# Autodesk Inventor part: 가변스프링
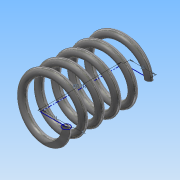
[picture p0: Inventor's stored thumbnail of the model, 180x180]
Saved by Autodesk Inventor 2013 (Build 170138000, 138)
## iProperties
Created: 2019-10
Part Number: 가변스프링
Material: 스테인리스강
Document SubType Name: Modeling
Designer: Administrator
Density: 8.08 g/cm^3
Mass: 147.816 g
Surface Area: 124.166 cm^2
Volume: 18.294 cm^3
Author: Administrator
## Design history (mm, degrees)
sketch "스케치1"
  geometry: L1 (0, 0)-(21, 0); L2 (0, 0)-(0, 67.25); L3 (0, 67.25)-(21, 67.25); C1 r 3 at (21, 0)
  constraints: 6 end point, 2 perpendicular, 1 centre point, 1 coincident, 1 horizontal
  dimensions: "d0" = 21 distance of L1.start L1.end; "d1" = 67.25 distance of L1.start L2.end (derived); "d2" = 21 distance of L2.end L3.end; "d3" = 6 diameter of C1
feature "코일1" pitch "d4" = 10; turns "d6" = 5; dims "d5" = 67.25 (= d1), "d7" = 0, angle "d8" = 90 deg, angle "d9" = 90 deg, "d10" = 0, "d11" = 0
sketch "스케치2"
  geometry: L1 (67.25, 25)-(0, 25); L2 (0, 25)-(0, -25); L3 (0, -25)-(67.25, -25); L4 (67.25, -25)-(67.25, 25); 2 further points
  constraints: 8 end point, 2 parallel, 1 coincident, 1 horizontal, 1 midpoint, 1 perpendicular
  dimensions: "d12" = 50 distance of L3.end L1.start; "d14" = 67.25 distance of L2.end L3.end (= d1)
extrude "돌출1" sketch "스케치2" stored distance "d15" = 0; taper "d16" = 0 deg
node "솔리드1"
